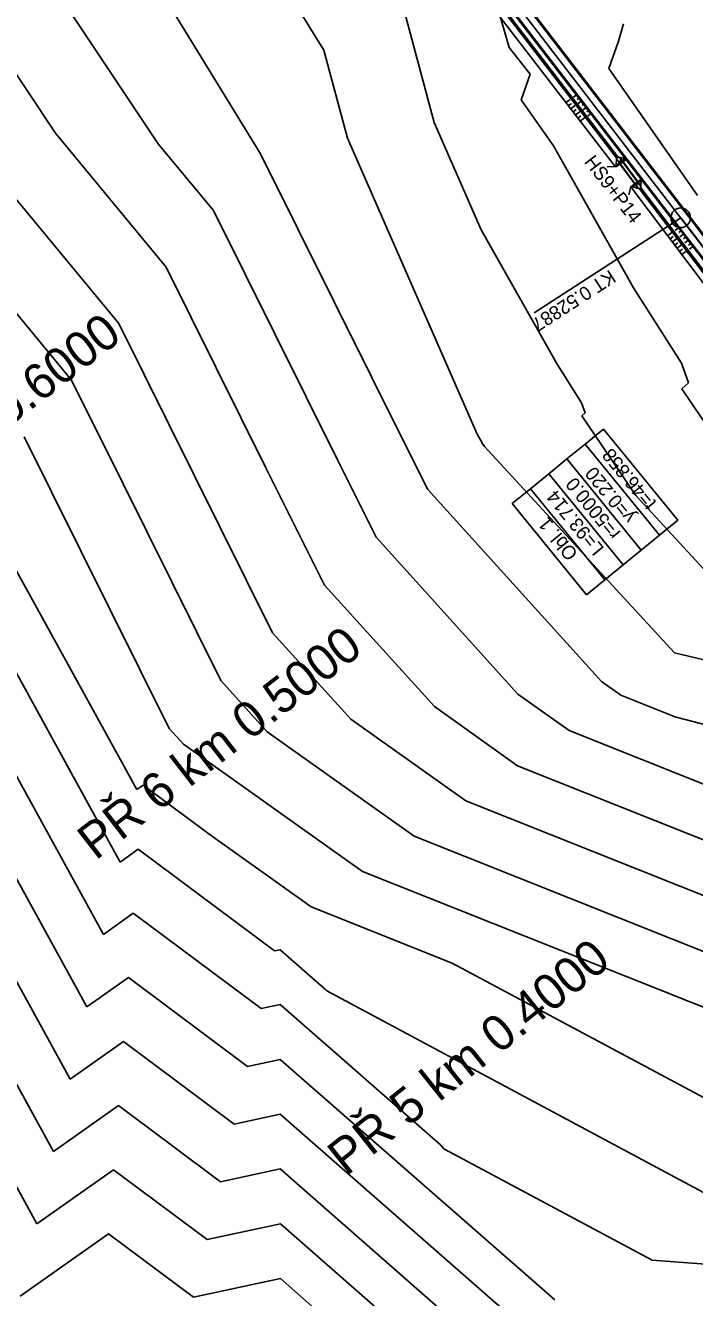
# Model space of a CAD drawing. Extents: x -549238 to -546764, y -1036895 to -1033794.
# Drawn here: x -548401.7 to -548231.1, y -1035300.1 to -1034975.5 of the extents above; entities that cross this region are included whole.
import ezdxf

# ---------------------------------------------------------------- set-up
doc = ezdxf.new("R2010")
doc.units = 0
for name, color, linetype in [('hlavni_vrst', 7, 'Continuous'), ('norm_vrst', 7, 'Continuous'), ('POLYGONY_SITUACE_PO', 7, 'Continuous'), ('u_prikop_C12', 7, 'Continuous'), ('x_navrh_C12', 7, 'Continuous'), ('x_osa_C12', 7, 'Continuous'), ('x_popis_C12', 7, 'Continuous'), ('x_popis_oblouky_C12', 7, 'Continuous'), ('x_popis_pricne_rezy_C12', 7, 'Continuous'), ('x_propustek', 7, 'Continuous')]:
    doc.layers.add(name, color=color, linetype=linetype)

msp = doc.modelspace()

# ---------------------------------------------------------------- linework, layer by layer
at = {"layer": 'hlavni_vrst'}
for p, q in [((-548325.66, -1034981.81), (-548350.92, -1034940.67)), ((-548319.63, -1035004.27), (-548325.66, -1034981.81)), ((-548390, -1035066.03), (-548446.34, -1034997.78)), ((-548286.55, -1035079.75), (-548319.63, -1035004.27)), ((-548376.85, -1035092.43), (-548390, -1035066.03)), ((-548285.63, -1035081.39), (-548286.55, -1035079.75)), ((-548285.33, -1035081.86), (-548285.63, -1035081.39)), ((-548285.28, -1035081.98), (-548285.33, -1035081.86)), ((-548285.32, -1035082.01), (-548285.28, -1035081.98)), ((-548284.67, -1035082.98), (-548285.32, -1035082.01)), ((-548236.21, -1035135.54), (-548284.67, -1035082.98)), ((-548351.89, -1035142.66), (-548376.85, -1035092.43)), ((-548173.36, -1035150.54), (-548236.21, -1035135.54)), ((-548340.1, -1035155.69), (-548351.89, -1035142.66)), ((-548302.57, -1035182.36), (-548340.1, -1035155.69)), ((-548386.12, -1035225.87), (-548420.65, -1035162.96)), ((-548194.87, -1035225.3), (-548302.57, -1035182.36)), ((-548375.5, -1035218.38), (-548386.12, -1035225.87)), ((-548345.09, -1035241.08), (-548375.5, -1035218.38)), ((-548336.78, -1035239.3), (-548345.09, -1035241.08)), ((-548266.71, -1035300.68), (-548336.78, -1035239.3))]:
    msp.add_line(p, q, dxfattribs=at)
at = {"layer": 'norm_vrst'}
for p, q in [((-548278.35, -1034981.13), (-548292.99, -1034930.32)), ((-548341.75, -1035008.31), (-548379.76, -1034946.38)), ((-548367.9, -1035005.68), (-548401.52, -1034955.28)), ((-548297.51, -1035000.24), (-548309.57, -1034955.32)), ((-548394.04, -1035003.04), (-548418.56, -1034966.31)), ((-548250.47, -1034979.54), (-548249.2, -1034975.11)), ((-548272.98, -1034987.99), (-548278.35, -1034981.13)), ((-548252.94, -1034986.52), (-548250.47, -1034979.54)), ((-548275.29, -1034994.5), (-548272.98, -1034987.99)), ((-548230.34, -1035018.92), (-548252.94, -1034986.52)), ((-548267.08, -1035006.27), (-548275.29, -1034994.5)), ((-548377.94, -1035051.6), (-548420.19, -1035000.41)), ((-548285.5, -1035027.64), (-548297.51, -1035000.24)), ((-548365.87, -1035037.17), (-548394.04, -1035003.04)), ((-548353.81, -1035022.74), (-548367.9, -1035005.68)), ((-548246.66, -1035042.42), (-548267.08, -1035006.27)), ((-548341.75, -1035008.31), (-548341.75, -1035008.31)), ((-548303.92, -1035084.29), (-548341.75, -1035008.31)), ((-548341.75, -1035008.31), (-548341.75, -1035008.31)), ((-548341.75, -1035008.31), (-548341.75, -1035008.31)), ((-548341.75, -1035008.31), (-548341.75, -1035008.31)), ((-548322.15, -1035086.33), (-548353.81, -1035022.74)), ((-548266.14, -1035061.9), (-548285.5, -1035027.64)), ((-548340.39, -1035088.36), (-548365.87, -1035037.17)), ((-548234.43, -1035061.72), (-548246.66, -1035042.42)), ((-548358.62, -1035090.4), (-548377.94, -1035051.6)), ((-548259.88, -1035071.79), (-548266.14, -1035061.9)), ((-548232.64, -1035066.7), (-548234.43, -1035061.72)), ((-548234.31, -1035068.19), (-548232.64, -1035066.7)), ((-548207.48, -1035107.98), (-548234.31, -1035068.19)), ((-548258.96, -1035074.34), (-548259.88, -1035071.79)), ((-548259.82, -1035075.1), (-548258.96, -1035074.34)), ((-548246.07, -1035095.48), (-548259.82, -1035075.1)), ((-548395.09, -1035094.47), (-548402.06, -1035080.46)), ((-548299.13, -1035093.93), (-548303.92, -1035084.29)), ((-548325.51, -1035118.29), (-548340.39, -1035088.36)), ((-548312.32, -1035106.11), (-548322.15, -1035086.33)), ((-548338.7, -1035130.48), (-548358.62, -1035090.4)), ((-548365.08, -1035154.84), (-548395.09, -1035094.47)), ((-548254.8, -1035142.92), (-548299.13, -1035093.93)), ((-548221.72, -1035121.89), (-548246.07, -1035095.48)), ((-548276.12, -1035146.11), (-548312.32, -1035106.11)), ((-548373.36, -1035170.48), (-548407.15, -1035108.92)), ((-548377.61, -1035188.94), (-548417.19, -1035116.83)), ((-548297.45, -1035149.3), (-548325.51, -1035118.29)), ((-548318.77, -1035152.5), (-548338.7, -1035130.48)), ((-548381.87, -1035207.4), (-548418.92, -1035139.9)), ((-548249.9, -1035146.4), (-548254.8, -1035142.92)), ((-548263.07, -1035155.39), (-548276.12, -1035146.11)), ((-548235.85, -1035152), (-548249.9, -1035146.4)), ((-548276.24, -1035164.38), (-548297.45, -1035149.3)), ((-548289.41, -1035173.37), (-548318.77, -1035152.5)), ((-548235.8, -1035151.97), (-548235.85, -1035152)), ((-548200.97, -1035161.06), (-548235.8, -1035151.97)), ((-548361.42, -1035158.88), (-548365.08, -1035154.84)), ((-548225.61, -1035170.32), (-548263.07, -1035155.39)), ((-548315.74, -1035191.35), (-548361.42, -1035158.88)), ((-548215.36, -1035188.65), (-548276.24, -1035164.38)), ((-548371.71, -1035169.32), (-548373.36, -1035170.48)), ((-548354.66, -1035182.04), (-548371.71, -1035169.32)), ((-548205.12, -1035206.97), (-548289.41, -1035173.37)), ((-548328.91, -1035200.35), (-548354.66, -1035182.04)), ((-548390.37, -1035244.33), (-548422.38, -1035186.02)), ((-548372.98, -1035185.67), (-548377.61, -1035188.94)), ((-548338.19, -1035211.63), (-548372.98, -1035185.67)), ((-548219.68, -1035229.65), (-548315.74, -1035191.35)), ((-548374.24, -1035202.03), (-548381.87, -1035207.4)), ((-548341.64, -1035226.35), (-548374.24, -1035202.03)), ((-548292.89, -1035214.71), (-548328.91, -1035200.35)), ((-548394.62, -1035262.8), (-548424.11, -1035209.09)), ((-548336.8, -1035211.33), (-548338.19, -1035211.63)), ((-548325.13, -1035221.56), (-548336.8, -1035211.33)), ((-548210.93, -1035258.6), (-548292.89, -1035214.71)), ((-548324.86, -1035221.85), (-548325.13, -1035221.56)), ((-548226.43, -1035274.57), (-548324.86, -1035221.85)), ((-548336.79, -1035225.31), (-548341.64, -1035226.35)), ((-548295.92, -1035261.12), (-548336.79, -1035225.31)), ((-548398.88, -1035281.26), (-548425.84, -1035232.15)), ((-548376.76, -1035234.74), (-548390.37, -1035244.33)), ((-548348.53, -1035255.8), (-548376.76, -1035234.74)), ((-548378.02, -1035251.1), (-548394.62, -1035262.8)), ((-548351.98, -1035270.53), (-548378.02, -1035251.1)), ((-548336.76, -1035253.28), (-548348.53, -1035255.8)), ((-548265.98, -1035315.28), (-548336.76, -1035253.28)), ((-548295, -1035262.11), (-548295.92, -1035261.12)), ((-548241.92, -1035290.54), (-548295, -1035262.11)), ((-548336.75, -1035267.26), (-548351.98, -1035270.53)), ((-548273.28, -1035322.85), (-548336.75, -1035267.26)), ((-548379.28, -1035267.45), (-548398.88, -1035281.26)), ((-548355.43, -1035285.25), (-548379.28, -1035267.45)), ((-548336.73, -1035281.24), (-548355.43, -1035285.25)), ((-548280.59, -1035330.42), (-548336.73, -1035281.24)), ((-548380.55, -1035283.81), (-548403.13, -1035299.73)), ((-548358.88, -1035299.98), (-548380.55, -1035283.81)), ((-548143.03, -1035297.88), (-548241.92, -1035290.54)), ((-548336.72, -1035295.22), (-548358.88, -1035299.98)), ((-548287.89, -1035337.99), (-548336.72, -1035295.22))]:
    msp.add_line(p, q, dxfattribs=at)
at = {"layer": 'POLYGONY_SITUACE_PO'}
msp.add_circle((-548234.61, -1035024.58), 2.5, dxfattribs=at)
at = {"layer": 'u_prikop_C12'}
for p, q in [((-548734.21, -1034380.33), (-548250.98, -1035009.26)), ((-548733.99, -1034379.97), (-548250.64, -1035009.01)), ((-548732.7, -1034385.01), (-548251.32, -1035011.54)), ((-548263.88, -1034995.19), (-548262.82, -1034994.37)), ((-548261.2, -1034993.26), (-548261.95, -1034993.84)), ((-548260.59, -1034994.05), (-548261, -1034994.37)), ((-548263.27, -1034995.98), (-548262.5, -1034995.39)), ((-548262.66, -1034996.77), (-548261.59, -1034995.95)), ((-548262.05, -1034997.57), (-548261.29, -1034996.98)), ((-548261.44, -1034998.36), (-548260.37, -1034997.54)), ((-548259.98, -1034994.85), (-548260.73, -1034995.43)), ((-548259.37, -1034995.64), (-548259.79, -1034995.97)), ((-548258.76, -1034996.43), (-548259.51, -1034997.01)), ((-548258.15, -1034997.23), (-548258.58, -1034997.56)), ((-548260.83, -1034999.15), (-548260.07, -1034998.57)), ((-548260.22, -1034999.95), (-548259.15, -1034999.12)), ((-548257.54, -1034998.02), (-548258.29, -1034998.6)), ((-548247.36, -1035016.68), (-548210.54, -1035065.56)), ((-548245.11, -1035017.18), (-548208.81, -1035065.18)), ((-548244.77, -1035016.92), (-548208.49, -1035064.94)), ((-548237.95, -1035029.18), (-548236.89, -1035028.36)), ((-548237.34, -1035029.97), (-548236.58, -1035029.38)), ((-548236.73, -1035030.76), (-548235.67, -1035029.94)), ((-548235.27, -1035027.25), (-548236.02, -1035027.83)), ((-548234.66, -1035028.04), (-548235.08, -1035028.36)), ((-548234.05, -1035028.84), (-548234.8, -1035029.42)), ((-548233.44, -1035029.63), (-548233.87, -1035029.96)), ((-548236.12, -1035031.56), (-548235.36, -1035030.97)), ((-548235.51, -1035032.35), (-548234.44, -1035031.53)), ((-548234.9, -1035033.14), (-548234.15, -1035032.56)), ((-548234.29, -1035033.93), (-548233.22, -1035033.11)), ((-548232.83, -1035030.42), (-548233.59, -1035031)), ((-548232.22, -1035031.22), (-548232.66, -1035031.55)), ((-548231.61, -1035032.01), (-548232.37, -1035032.59))]:
    msp.add_line(p, q, dxfattribs=at)
at = {"layer": 'x_navrh_C12'}
for p, q in [((-548741.44, -1034362.06), (-548233.23, -1035023.51)), ((-548743.07, -1034365.69), (-548236, -1035025.64)), ((-548732.04, -1034380.45), (-548236.2, -1035025.8)), ((-548414.25, -1034787.5), (-548233.03, -1035023.36))]:
    msp.add_line(p, q, dxfattribs=at)
for points in [[(-548248.54, -1035009.73), (-548251, -1035011.53), (-548253.34, -1035011.6)], [(-548244.7, -1035014.74), (-548247.35, -1035016.65), (-548247.83, -1035018.76)]]:
    msp.add_lwpolyline(points, dxfattribs=at)
for radius, end in [(4998.25, 218.61031), (4998, 217.82833), (5002, 218.61031), (5001.75, 218.61031)]:
    msp.add_arc((-544269.78, -1031978.25), radius, 217.53642, end, dxfattribs=at)
at = {"layer": 'x_osa_C12'}
msp.add_lwpolyline([(-548743.02, -1034362.88), (-548206.06, -1035061.74)], dxfattribs=at)
msp.add_arc((-544269.78, -1031978.25), 5000, 217.53642, 218.61031, dxfattribs=at)
at = {"layer": 'x_popis_oblouky_C12'}
msp.add_lwpolyline([(-548272.03, -1035048.8), (-548234.61, -1035024.58)], dxfattribs=at)
for points in [[(-548240.02, -1035105.56), (-548258.99, -1035082.32), (-548254.34, -1035078.53), (-548235.37, -1035101.77)], [(-548244.67, -1035109.35), (-548263.64, -1035086.11), (-548258.99, -1035082.32), (-548240.02, -1035105.56)], [(-548249.32, -1035113.15), (-548268.29, -1035089.91), (-548263.64, -1035086.11), (-548244.67, -1035109.35)], [(-548253.97, -1035116.94), (-548272.94, -1035093.7), (-548268.29, -1035089.91), (-548249.32, -1035113.15)], [(-548258.61, -1035120.74), (-548277.58, -1035097.49), (-548272.94, -1035093.7), (-548253.97, -1035116.94)]]:
    msp.add_lwpolyline(points, close=True, dxfattribs=at)
at = {"layer": 'x_propustek'}
for p, q in [((-548251.04, -1035011.34), (-548250.98, -1035009.26)), ((-548251.04, -1035011.34), (-548248.63, -1035009.55)), ((-548250.64, -1035009.01), (-548250.98, -1035009.26)), ((-548250.66, -1035011.05), (-548250.9, -1035010.73)), ((-548250.73, -1035009.93), (-548245.67, -1035016.75)), ((-548250.58, -1035011), (-548250.7, -1035010.83)), ((-548250.64, -1035009.01), (-548248.63, -1035009.55)), ((-548250.23, -1035010.73), (-548245.73, -1035016.8)), ((-548250.07, -1035009.44), (-548245.01, -1035016.26)), ((-548250.01, -1035009.39), (-548244.95, -1035016.22)), ((-548249.01, -1035009.83), (-548249.25, -1035009.51)), ((-548249.09, -1035009.89), (-548249.21, -1035009.73)), ((-548248.93, -1035009.77), (-548249.05, -1035009.61)), ((-548250.74, -1035011.11), (-548250.86, -1035010.95)), ((-548244.7, -1035014.85), (-548247.11, -1035016.64)), ((-548245.11, -1035017.18), (-548247.11, -1035016.64)), ((-548246.81, -1035016.42), (-548246.69, -1035016.58)), ((-548246.73, -1035016.36), (-548246.49, -1035016.68)), ((-548246.65, -1035016.3), (-548246.53, -1035016.46)), ((-548245.16, -1035015.19), (-548245.04, -1035015.35)), ((-548245.11, -1035017.18), (-548244.77, -1035016.92)), ((-548245.08, -1035015.13), (-548244.84, -1035015.45)), ((-548245, -1035015.07), (-548244.88, -1035015.23)), ((-548244.7, -1035014.85), (-548244.77, -1035016.92))]:
    msp.add_line(p, q, dxfattribs=at)
for points in [[(-548250.85, -1035009.08), (-548250.86, -1035009.09), (-548250.87, -1035009.1), (-548250.9, -1035009.12), (-548250.91, -1035009.13), (-548250.94, -1035009.17), (-548250.95, -1035009.2), (-548250.99, -1035009.3), (-548251, -1035009.37), (-548250.99, -1035009.54), (-548250.97, -1035009.63), (-548250.9, -1035009.8), (-548250.85, -1035009.89), (-548250.73, -1035010.05), (-548250.67, -1035010.12), (-548250.52, -1035010.24), (-548250.44, -1035010.29), (-548250.28, -1035010.34), (-548250.2, -1035010.36), (-548250.12, -1035010.35), (-548250.1, -1035010.35), (-548250.07, -1035010.34), (-548250.05, -1035010.34), (-548250.01, -1035010.32), (-548249.98, -1035010.3), (-548249.95, -1035010.29)], [(-548250.81, -1035009.14), (-548250.82, -1035009.15), (-548250.84, -1035009.17), (-548250.87, -1035009.21), (-548250.88, -1035009.23), (-548250.9, -1035009.28), (-548250.91, -1035009.31), (-548250.92, -1035009.38), (-548250.92, -1035009.41), (-548250.92, -1035009.49), (-548250.91, -1035009.53), (-548250.9, -1035009.61), (-548250.88, -1035009.65), (-548250.84, -1035009.77), (-548250.79, -1035009.85), (-548250.68, -1035010), (-548250.61, -1035010.07), (-548250.51, -1035010.15), (-548250.47, -1035010.18), (-548250.4, -1035010.22), (-548250.37, -1035010.23), (-548250.3, -1035010.26), (-548250.26, -1035010.27), (-548250.2, -1035010.28), (-548250.17, -1035010.28), (-548250.11, -1035010.27), (-548250.09, -1035010.27), (-548250.04, -1035010.25), (-548250.02, -1035010.24), (-548249.98, -1035010.21), (-548249.96, -1035010.19), (-548249.93, -1035010.15), (-548249.92, -1035010.13), (-548249.9, -1035010.08), (-548249.89, -1035010.05), (-548249.88, -1035009.98), (-548249.88, -1035009.95), (-548249.89, -1035009.87), (-548249.89, -1035009.84), (-548249.91, -1035009.76), (-548249.92, -1035009.71), (-548249.97, -1035009.59), (-548250.01, -1035009.51), (-548250.13, -1035009.36), (-548250.19, -1035009.29), (-548250.29, -1035009.21), (-548250.33, -1035009.19), (-548250.4, -1035009.15), (-548250.44, -1035009.13), (-548250.51, -1035009.1), (-548250.54, -1035009.1), (-548250.61, -1035009.09), (-548250.64, -1035009.09), (-548250.69, -1035009.09), (-548250.72, -1035009.1), (-548250.77, -1035009.11), (-548250.79, -1035009.12), (-548250.81, -1035009.14)], [(-548249.95, -1035010.29), (-548249.94, -1035010.28), (-548249.93, -1035010.27), (-548249.91, -1035010.24), (-548249.9, -1035010.23), (-548249.87, -1035010.19), (-548249.85, -1035010.16), (-548249.82, -1035010.07), (-548249.8, -1035009.99), (-548249.81, -1035009.82), (-548249.83, -1035009.73), (-548249.9, -1035009.56), (-548249.95, -1035009.47), (-548250.07, -1035009.31), (-548250.14, -1035009.24), (-548250.29, -1035009.12), (-548250.37, -1035009.08), (-548250.53, -1035009.02), (-548250.6, -1035009.01), (-548250.69, -1035009.01), (-548250.7, -1035009.02), (-548250.74, -1035009.02), (-548250.75, -1035009.03), (-548250.8, -1035009.04), (-548250.83, -1035009.06), (-548250.85, -1035009.08)], [(-548245.79, -1035015.9), (-548245.8, -1035015.91), (-548245.81, -1035015.92), (-548245.84, -1035015.94), (-548245.85, -1035015.96), (-548245.88, -1035015.99), (-548245.89, -1035016.02), (-548245.93, -1035016.12), (-548245.94, -1035016.2), (-548245.93, -1035016.36), (-548245.91, -1035016.45), (-548245.84, -1035016.63), (-548245.79, -1035016.72), (-548245.67, -1035016.88), (-548245.6, -1035016.95), (-548245.46, -1035017.07), (-548245.38, -1035017.11), (-548245.22, -1035017.17), (-548245.14, -1035017.18), (-548245.06, -1035017.17), (-548245.04, -1035017.17), (-548245.01, -1035017.16), (-548244.99, -1035017.16), (-548244.95, -1035017.14), (-548244.92, -1035017.13), (-548244.89, -1035017.11)], [(-548244.94, -1035017.05), (-548244.92, -1035017.04), (-548244.9, -1035017.02), (-548244.87, -1035016.98), (-548244.86, -1035016.96), (-548244.84, -1035016.9), (-548244.83, -1035016.87), (-548244.82, -1035016.81), (-548244.82, -1035016.77), (-548244.82, -1035016.7), (-548244.83, -1035016.66), (-548244.85, -1035016.58), (-548244.86, -1035016.54), (-548244.91, -1035016.42), (-548244.95, -1035016.34), (-548245.07, -1035016.18), (-548245.13, -1035016.12), (-548245.23, -1035016.04), (-548245.27, -1035016.01), (-548245.34, -1035015.97), (-548245.38, -1035015.96), (-548245.45, -1035015.93), (-548245.48, -1035015.92), (-548245.55, -1035015.91), (-548245.58, -1035015.91), (-548245.63, -1035015.91), (-548245.66, -1035015.92), (-548245.7, -1035015.94), (-548245.73, -1035015.95), (-548245.76, -1035015.98), (-548245.78, -1035015.99), (-548245.81, -1035016.03), (-548245.82, -1035016.06), (-548245.84, -1035016.11), (-548245.85, -1035016.14), (-548245.86, -1035016.2), (-548245.86, -1035016.24), (-548245.86, -1035016.31), (-548245.85, -1035016.35), (-548245.84, -1035016.43), (-548245.82, -1035016.47), (-548245.78, -1035016.6), (-548245.73, -1035016.68), (-548245.62, -1035016.83), (-548245.55, -1035016.89), (-548245.45, -1035016.98), (-548245.41, -1035017), (-548245.34, -1035017.04), (-548245.31, -1035017.06), (-548245.24, -1035017.08), (-548245.2, -1035017.09), (-548245.14, -1035017.1), (-548245.11, -1035017.1), (-548245.05, -1035017.1), (-548245.03, -1035017.09), (-548244.98, -1035017.08), (-548244.96, -1035017.06), (-548244.94, -1035017.05)], [(-548244.89, -1035017.11), (-548244.88, -1035017.1), (-548244.87, -1035017.09), (-548244.85, -1035017.07), (-548244.84, -1035017.06), (-548244.81, -1035017.02), (-548244.79, -1035016.99), (-548244.75, -1035016.89), (-548244.74, -1035016.82), (-548244.75, -1035016.65), (-548244.77, -1035016.56), (-548244.84, -1035016.38), (-548244.89, -1035016.3), (-548245.01, -1035016.13), (-548245.08, -1035016.06), (-548245.23, -1035015.95), (-548245.31, -1035015.9), (-548245.47, -1035015.84), (-548245.54, -1035015.83), (-548245.63, -1035015.84), (-548245.64, -1035015.84), (-548245.68, -1035015.85), (-548245.69, -1035015.85), (-548245.74, -1035015.87), (-548245.76, -1035015.88), (-548245.79, -1035015.9)]]:
    msp.add_open_spline(points, degree=3, dxfattribs=at)

# ---------------------------------------------------------------- texts
at = {"layer": 'x_popis_C12'}
msp.add_text('HS9+P14', height=3.5, rotation=307.6216, dxfattribs=at).set_placement((-548259.39, -1035010.35))
at = {"layer": 'x_popis_oblouky_C12'}
for s, rotation, p in [('KT 0.52887', 212.9133, (-548252.69, -1035037.73)), ('t=46.858', 129.2424, (-548240.6, -1035097.27)), ('y=0.220', 129.2424, (-548245.96, -1035100.75)), ('r=5000.0', 129.2424, (-548249.75, -1035104.89)), ('L=93.714', 129.2424, (-548253.97, -1035108.94)), ('Obl. 1', 129.2424, (-548260.65, -1035110.25))]:
    msp.add_text(s, height=3.5, rotation=rotation, dxfattribs=at).set_placement(p)
at = {"layer": 'x_popis_pricne_rezy_C12'}
for s, rotation, p in [('PŘ 7 km 0.6000', 37.5364, (-548445.64, -1035108.45)), ('PŘ 6 km 0.5000', 37.8673, (-548383.84, -1035188.67)), ('PŘ 5 km 0.4000', 38.6103, (-548319.92, -1035269.22)), ('PŘ 4 km 0.3000', 38.6103, (-548257.52, -1035347.36))]:
    msp.add_text(s, height=9.0627, rotation=rotation, dxfattribs=at).set_placement(p)

doc.saveas('drawing.dxf')
